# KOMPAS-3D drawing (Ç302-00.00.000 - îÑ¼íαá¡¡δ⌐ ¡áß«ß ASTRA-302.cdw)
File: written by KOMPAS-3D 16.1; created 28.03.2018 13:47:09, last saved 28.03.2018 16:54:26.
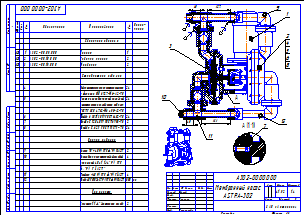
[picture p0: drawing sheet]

Sheet 1: A3, landscape

Title block, sheet 1: name: Мембранный насос / ASTRA-302; designation: А302-00.00.000; mass: 41,52; scale: 1:4; sheets: 1; organisation: ЗАО «Астерион»; sheet format: A3; stored path: Z:\Мембранные насосы\Мембранный электропривод\А302-00.00.000 - ASTRA-302 (МЭ200)\Чертежи\А302-00.00.000 - Мембранный насос ASTRA-302.cdw; drawn by: Милов; technical control: Лучихин; approved by: Григорьева

Views: Вид 1, Местный разрез 1, Снизу, Выносной элемент 3, Вид 4, Вид:1, Выносной элемент А, Выносной элемент
Referenced files in Z:\Мембранные насосы\Мембранный электропривод\А302-00.00.000 - ASTRA-302 (МЭ200)\3Д\: А302-00.20.004 - Вал.m3d, А302-00.12.001 - Крышка.m3d, А302-00.10.001 - Седло.m3d, А302-00.05.001 - Основание.m3d, А302-00.20.003 - Ползун.m3d, А302-00.30.001 - Прижим.m3d, А302-00.35.001 - Труба 140х140х4.m3d, А302-00.05.002 - Ловитель.m3d, А302-00.31.001 - Корпус.m3d, А302-00.20.001 - Основание.m3d, А302-00.10.002 3Д - Стакан.m3d, А302-00.15.003 - Шайба.m3d, А302-00.15.001 - Мембрана.m3d, А302-00.15.002 - Упор.m3d, А302-00.20.002 - Эксцентрик.m3d, А302-00.00.000  - Мембранный насос ASTRA-302.a3d, А302-00.35.002 - Пластина.m3d, А302-00.35.000 - Фланец.a3d, А302-00.20.000 - Мотор-редуктор.a3d, А302-00.05.000 - Корпус.a3d, А302-00.15.001 - Мембрана.a3d, А302-00.12.000 - Крышка.a3d, А302-00.11.001 - Колена 45гр ф40.m3d, А302-00.31.000 - Корпус.a3d, А302-00.11.000 - Крышка рабочей камеры.a3d, А302-00.30.000 - Прижим.a3d, А302-00.10.000 - Рабочая камера.a3d
Referenced files in Z:\1 ПКИ 3D\Полипропиленовые фитинги, трубы\Трубы\: Труба 40 PN10 S=3,7 FV PPR ф. FV PLAST.m3d
Referenced files in Z:\1 ПКИ 3D\Полипропиленовые фитинги, трубы\: Труба ф40х3,7 (PN10) FV PPR ф. FV PLAST.m3d, Тройник 40 FV PPR ф. FV PLAST.m3d, Переходник с пластмассовой резьбой наружной 40х1 1_4 FV PPR ф.FV Plast.m3d, Колено 90гр 40 FV PPR ф. FV PLAST.m3d, Колено 45гр 40 FV PPR ф. FV PLAST.m3d
Referenced files in Z:\1 ПКИ 3D\РТИ\Кольца ГОСТ 9833-76\: Кольцо 054-058-25 EPDM ГОСТ 9833-76.m3d, Кольцо 058-062-25 EPDM ГОСТ 9833-76.m3d
Referenced files in C:\Program Files\ASCON\KOMPAS-3D V16\Libs\PartLib\DATA\VAULT\Methods\kompas\3d\: PLib_Washer_1_712.m3d, PLib_Bolt_1_900.m3d, PLib_Washer_2_712.m3d
Referenced files in Z:\1 ПКИ 3D\РТИ\Кольца уплотнительные  плоские\: Кольцо плоское уплотнительное 5-13-10 Ф4.m3d, Кольцо плоское уплотнительное 7-18-10 Ф4.m3d
Referenced files in C:\Program Files\ASCON\KOMPAS-3D V16\Libs\PartLib\DATA\vault\Methods\Kompas\3D\: PLib_Bolt_1_ISO_1100.m3d, PLib_Check_spring_rings_GOST_13942_911.m3d, PLib_Nut_OST92_900.m3d, PLib_Screw_DIN_7984_1500.m3d, PLib_Key_prismatic_712.m3d, PLib_Nut_ISO_1100.m3d
Referenced files in D:\3Д модели\Крепеж\: Гайка шестигранная самостопорящаяся с фланцем DIN 6927-M6 - A2-70.m3d
Referenced files in Z:\Мембранные насосы\Мембранный электропривод\А302-00.00.000 - ASTRA-302 (МЭ200)\Чертежи\: А302-00.05.000 - Корпус.cdw, А302-00.10.000 - Рабочая камера.cdw
Referenced files in \\192.168.87.28\Konstructor_doc\Мембранные насосы\Мембранный электропривод\А302-00.00.000 - ASTRA-302 (МЭ200)\Чертежи\: А302-00.15.000 - Мембрана.cdw
Referenced files: graphic.tdp
Referenced files in Z:\1 ПКИ 3D\Двигатели\АИР\: Электродвигатель АИР 80А4 IM 3081 1,1кВт 1400 об..m3d
Referenced files in Z:\1 ПКИ 3D\Редуктора NMRW\Редукторы\: Редуктор NMRW 063.m3d, Червячный мотор-редуктор NMRV063 АИР80.a3d
Referenced files in Z:\1 ПКИ 3D\1 Крепеж стандартный\Подшипник\: Подшипник 52х25х15 62052RSH SKF.m3d
Referenced files in Z:\1 ПКИ 3D\2 Китай\: Шар PTFE ф45.m3d
Referenced files in D:\МЭ200\Макеты\: Заготовка стакан.m3d
Referenced files in Z:\2 Стандартные изделия 3D\Гайки\DIN 6927\: Гайка шестигранная самостопорящаяся с фланцем DIN 6927-M5 - A2-70.m3d
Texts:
  Заглушка 1 1/4" внутренняя резьба
  Корпус
  Мембрана
  Шайба C 12.04.019 ГОСТ 6958-78
  Крепежное изделие ГОСТ
  Шайба
  ГОСТ
  Сталь 20 ГОСТ 1050-2013
  Рабочая камера
  Колено 90   40 FV PPR ф. "FV PLAST"
  Колено 90@1~ @2~40 FV PPR ф. "FV PLAST"
  Тройник  40 FV PPR ф. "FV PLAST"
  Тройник @2~40 FV PPR ф. "FV PLAST"
  Труба 40 PN10 S=3,7 FV PPR ф. FV PLAST
  Переходник с пластмассовой резьбой
  наружной 40х1 1/4" FV PPR
  ф. "FV PLAST"
  Переходник с пластмассовой резьбой  / наружной 40х1 1/4" FV PPR  / ф. "FV PLAST"
  Шайба C.6.21 ГОСТ 11371-78
  Сталь 12Х18Н10Т ГОСТ 5632-72
  Шайба 6 30Х13 019 ГОСТ 6402-70
  Сталь 30Х13 ГОСТ 5632-72
  Винт с цилиндрической головкой
  и шестигранным углублением под ключ
  ГОСТ Р ИСО  4762-М6 x 50-A2-70
  Винт с цилиндрической головкой и шестигранным углублением под ключ
  Р ИСО
  Нержавеющая сталь
  Гайка шестигранная самостопорящаяся
  с фланцем DIN 6927-M6-A2-70
  Гайка
  шестигранная
  самостопорящаяся
  фланцем
  DIN
  Винт с цилиндрической головкой и шестигранным углублением под ключ ГОСТ Р ИСО  4762-М6 x 50-A2-70
  Лит-Масса-Масштаб
  Материал-Предприятие
  Title Specification
  Body Specification ( left align )
  Body Specificaton ( centered )
  Поз.
  Кол.
  Приме-
  чание
  Таблица спецификации
  Электродвигатель АИР 80А4 IM 3081 1,1кВт 1400 об.
  Редуктор NMRW 063
  Червячный мотор-редуктор NMRV063 АИР80
  Основание
  Пластина
  Труба 140х140х4
  Фланец
  Эксцентрик
  Кольцо A25.65Г ГОСТ 13942-86
  Подшипник 52х25х15 62052RSH SKF
  Вал
  Ползун
  Шайба C.5.04.019 ГОСТ 11371-78
  Болт М5-6gx35.58.019 ГОСТ 7805-70
  Шайба 5 30Х13 019 ГОСТ 6402-70
  Гайка М5-6H.5.019 ГОСТ 5915-70
  Шайба C.8.04.019 ГОСТ 11371-78
  Шайба 8 30Х13 019 ГОСТ 6402-70
  Винт с цилиндрической головкой и шестигранным углублением под ключ ГОСТ Р ИСО 4762 - М8 x 20 - 6.8 - A9J
  Винт с цилиндрической головкой и шестигранным углублением под ключ ГОСТ Р ИСО 4762 - М8 x 35 - 6.8 - A9J
  Гайка М8-6H.5.019 ГОСТ 5915-70
  Шпонка 8x7x90 ГОСТ 23360-78
  Мотор-редуктор
  Ловитель
  Шайба C.8.21 ГОСТ 11371-78
  Шайба C 8.04.019 ГОСТ 6958-78
  Болт М8-6gx30.58.019 ГОСТ 7805-70
  Упор
  Болт с шестигранной головкой с фланцем ГОСТ Р 55739 - М5 x 30 - A2-70
  Гайка шестигранная самостопорящаяся с фланцем DIN 6927-M6 - A2-70
  Кольцо плоское уплотнительное 5-13-10 Ф4
  Болт с шестигранной головкой с фланцем ГОСТ Р 55739 - М8 x 30 - A2-70
  Кольцо плоское уплотнительное 7-18-10 Ф4
  Крышка
  Труба ф40х3,7 (PN10) FV PPR ф. FV PLAST
  Колено 45гр 40 FV PPR ф. FV PLAST
  Колено 45гр ф40
  Колено 90гр 40 FV PPR ф. FV PLAST
  Крышка рабочей камеры
  Седло
  Шар PTFE ф45
  Стакан
  Прижим
  Шайба C.5.21 ГОСТ 11371-78
  Шайба 5 30Х13 ГОСТ 6402-70
  Гайка шестигранная с фланцем ГОСТ Р ИСО 4161 - M5 - A2-70
  Гайка шестигранная самостопорящаяся с фланцем DIN 6927-M5 - A2-70
  Винт с цилиндрической головкой и шестигранным углублением под ключ ГОСТ Р ИСО 4762 - М5 x 35 - A2-70
  Кольцо 054-058-25 EPDM
  Кольцо 058-062-25 EPDM
  Тройник 40 FV PPR ф. FV PLAST
  Переходник с пластмассовой резьбой наружной 40х1 1/4" FV PPR ф."FV Plast"
  Винт с цилиндрической головкой и шестигранным углублением под ключ ГОСТ Р ИСО 4762 - М6 x 50 - A2-70
Dimensions and other numbers on the sheet: 1; 2; 4; 5; 6; 8; 3; 127; 161; 40; 9; 10; 11; 12; 7; 04; 40Х; 019; 800; 21; 58; 30Х13; 1:4; 41,52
